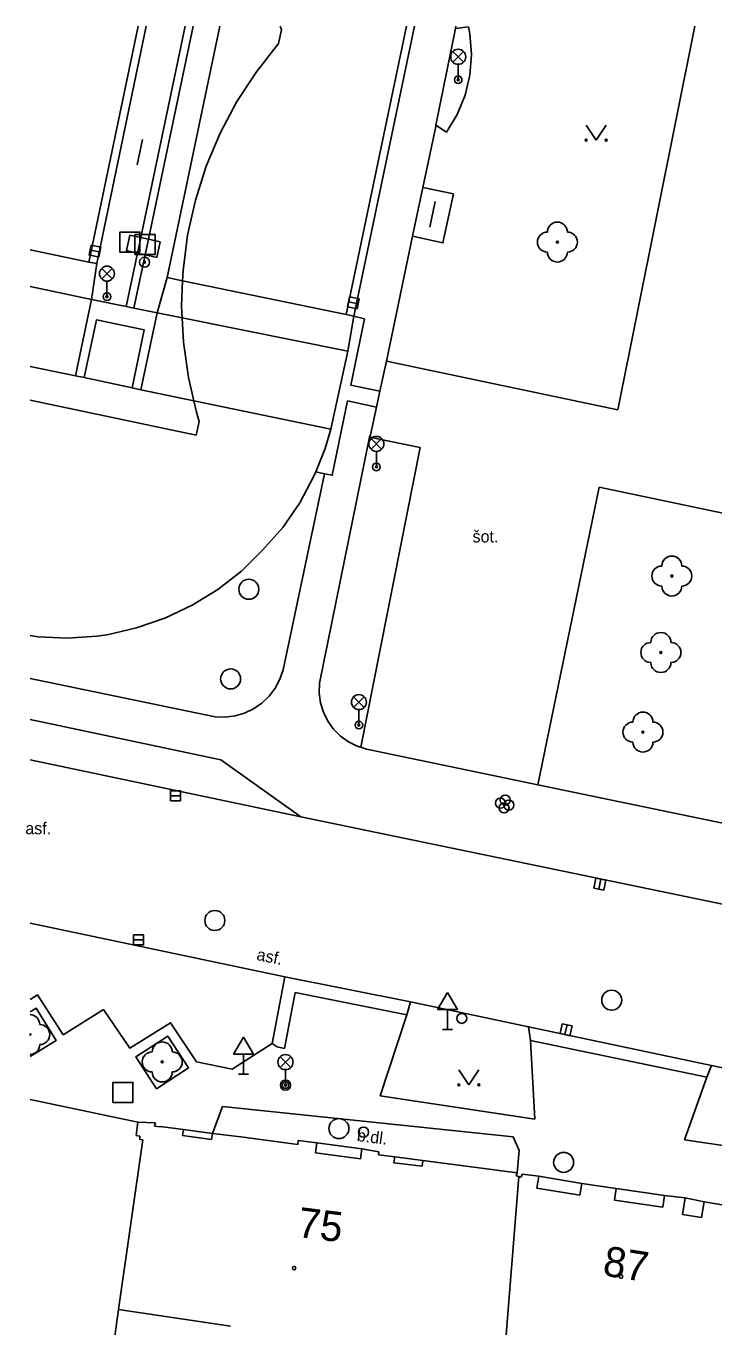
# Model space of a CAD drawing. Extents: x -642282 to -641982, y -1041678 to -1041427.
# Drawn here: x -642278.5 to -642244.2, y -1041493.9 to -1041428.9 of the extents above; entities that cross this region are included whole.
import ezdxf

# ---------------------------------------------------------------- set-up
doc = ezdxf.new("R2010")
doc.units = 0
for name, color, linetype in [('Budovy', 7, 'Continuous'), ('Neob_náplň-linie', 7, 'Continuous'), ('Popis povrchů', 7, 'Continuous'), ('Popis ČP_ ČE', 7, 'Continuous'), ('Rozhraní ploch 1', 7, 'Continuous'), ('Rozhraní ploch 2', 7, 'Continuous'), ('Sloupy_označník', 7, 'Continuous'), ('Zeleň - stromy', 7, 'Continuous'), ('Znaky doprava', 7, 'Continuous'), ('Znaky kanalizace', 7, 'Continuous'), ('Značky doprava', 7, 'Continuous'), ('Značky KM', 7, 'Continuous'), ('Značky předmětů', 7, 'Continuous'), ('Šachty ner_', 7, 'Continuous')]:
    doc.layers.add(name, color=color, linetype=linetype)

msp = doc.modelspace()

# ---------------------------------------------------------------- linework, layer by layer
at = {"layer": 'Budovy'}
for p, q in [((-642265.776, -1041429.092), (-642265.92, -1041429.777)), ((-642265.833, -1041428.899), (-642265.776, -1041429.092)), ((-642265.92, -1041429.777), (-642267.025, -1041431.182)), ((-642267.025, -1041431.182), (-642267.999, -1041432.68)), ((-642267.999, -1041432.68), (-642268.836, -1041434.259)), ((-642268.836, -1041434.259), (-642269.528, -1041435.907)), ((-642269.528, -1041435.907), (-642270.07, -1041437.61)), ((-642270.07, -1041437.61), (-642270.458, -1041439.355)), ((-642270.458, -1041439.355), (-642270.688, -1041441.127)), ((-642270.688, -1041441.127), (-642270.708, -1041441.64)), ((-642270.708, -1041441.64), (-642270.759, -1041442.913)), ((-642270.759, -1041442.913), (-642270.73, -1041443.493)), ((-642270.73, -1041443.493), (-642270.67, -1041444.698)), ((-642270.67, -1041444.698), (-642270.422, -1041446.467)), ((-642270.422, -1041446.467), (-642270.151, -1041447.631)), ((-642270.03, -1041449.35), (-642278.331, -1041447.61)), ((-642270.151, -1041447.631), (-642270.016, -1041448.208)), ((-642269.88, -1041448.67), (-642270.03, -1041449.35)), ((-642270.016, -1041448.208), (-642269.88, -1041448.67)), ((-642273.03, -1041484.37), (-642272.94, -1041483.7)), ((-642272.94, -1041483.7), (-642272.06, -1041483.74)), ((-642272.112, -1041483.9), (-642272.06, -1041483.74)), ((-642272.84, -1041484.4), (-642273.03, -1041484.37)), ((-642272.84, -1041484.56), (-642272.84, -1041484.4)), ((-642271.83, -1041483.941), (-642272.112, -1041483.9)), ((-642271.83, -1041483.92), (-642270.67, -1041484.07)), ((-642271.83, -1041483.92), (-642271.83, -1041483.941)), ((-642270.67, -1041484.07), (-642270.711, -1041484.367)), ((-642270.711, -1041484.367), (-642269.261, -1041484.567)), ((-642270.67, -1041484.07), (-642269.22, -1041484.27)), ((-642269.22, -1041484.27), (-642269.261, -1041484.567)), ((-642269.22, -1041484.27), (-642267.8, -1041484.44)), ((-642267.8, -1041484.44), (-642265.45, -1041484.75)), ((-642273.906, -1041493.066), (-642272.7, -1041484.58)), ((-642272.7, -1041484.58), (-642272.84, -1041484.56)), ((-642265.45, -1041484.75), (-642264.96, -1041484.81)), ((-642264.96, -1041484.81), (-642264.94, -1041484.62)), ((-642264.94, -1041484.62), (-642264, -1041484.74)), ((-642264, -1041484.74), (-642264.066, -1041485.236)), ((-642264, -1041484.74), (-642261.75, -1041485.04)), ((-642261.75, -1041485.04), (-642261.816, -1041485.536)), ((-642261.75, -1041485.04), (-642260.906, -1041485.181)), ((-642264.066, -1041485.236), (-642261.816, -1041485.536)), ((-642260.925, -1041485.326), (-642260.906, -1041485.181)), ((-642260.925, -1041485.326), (-642260.11, -1041485.43)), ((-642260.11, -1041485.43), (-642260.148, -1041485.728)), ((-642260.148, -1041485.728), (-642258.748, -1041485.908)), ((-642260.11, -1041485.43), (-642258.71, -1041485.61)), ((-642258.71, -1041485.61), (-642258.748, -1041485.908)), ((-642258.71, -1041485.61), (-642254, -1041486.24)), ((-642254, -1041486.24), (-642254.035, -1041486.386)), ((-642254.035, -1041486.386), (-642253.91, -1041486.416)), ((-642253.785, -1041486.446), (-642253.75, -1041486.3)), ((-642253.75, -1041486.3), (-642252.91, -1041486.4)), ((-642252.91, -1041486.4), (-642253.009, -1041486.992)), ((-642252.91, -1041486.4), (-642250.76, -1041486.76)), ((-642254.655, -1041495.751), (-642253.91, -1041486.416)), ((-642253.91, -1041486.416), (-642253.785, -1041486.446)), ((-642253.009, -1041486.992), (-642250.859, -1041487.352)), ((-642250.76, -1041486.76), (-642250.859, -1041487.352)), ((-642250.76, -1041486.76), (-642249.05, -1041487.01)), ((-642249.05, -1041487.01), (-642249.136, -1041487.604)), ((-642249.05, -1041487.01), (-642246.63, -1041487.36)), ((-642249.136, -1041487.604), (-642246.716, -1041487.954)), ((-642246.63, -1041487.36), (-642246.716, -1041487.954)), ((-642246.63, -1041487.36), (-642245.6, -1041487.48)), ((-642245.6, -1041487.48), (-642245.735, -1041488.315)), ((-642245.6, -1041487.48), (-642244.65, -1041487.68)), ((-642244.65, -1041487.68), (-642244.778, -1041488.47)), ((-642244.65, -1041487.68), (-642243.16, -1041487.93)), ((-642245.735, -1041488.315), (-642244.778, -1041488.47)), ((-642274.29, -1041495.77), (-642273.906, -1041493.066)), ((-642273.906, -1041493.066), (-642268.325, -1041493.892))]:
    msp.add_line(p, q, dxfattribs=at)
at = {"layer": 'Neob_náplň-linie'}
for p, q in [((-642272.98, -1041435.84), (-642272.71, -1041434.57)), ((-642258.36, -1041438.95), (-642258.09, -1041437.68))]:
    msp.add_line(p, q, dxfattribs=at)
at = {"layer": 'Rozhraní ploch 1'}
for p, q in [((-642275.39, -1041440.7), (-642272.934, -1041428.899)), ((-642271.48, -1041441.48), (-642268.852, -1041428.899)), ((-642259.121, -1041428.899), (-642262.15, -1041443.41)), ((-642257.08, -1041429.03), (-642257.052, -1041428.899)), ((-642257.08, -1041429.03), (-642256.42, -1041428.94)), ((-642258.05, -1041433.86), (-642257.52, -1041434.2)), ((-642260.515, -1041445.659), (-642259.22, -1041439.41)), ((-642275.39, -1041440.7), (-642278.331, -1041440.082)), ((-642275, -1041440.78), (-642275.39, -1041440.7)), ((-642275.27, -1041442.57), (-642275, -1041440.78)), ((-642271.99, -1041443.24), (-642271.48, -1041441.48)), ((-642270.708, -1041441.64), (-642271.48, -1041441.48)), ((-642278.331, -1041441.928), (-642275.27, -1041442.57)), ((-642262.54, -1041443.33), (-642270.708, -1041441.64)), ((-642275.27, -1041442.57), (-642276.07, -1041446.39)), ((-642271.99, -1041443.24), (-642272.79, -1041447.08)), ((-642271.99, -1041443.24), (-642270.73, -1041443.493)), ((-642270.73, -1041443.493), (-642262.46, -1041445.15)), ((-642276.07, -1041446.39), (-642278.331, -1041445.918)), ((-642260.86, -1041447.16), (-642260.515, -1041445.659)), ((-642263.3, -1041449.06), (-642270.151, -1041447.631)), ((-642261.371, -1041449.461), (-642261.32, -1041449.33)), ((-642263.87, -1041461.76), (-642261.371, -1041449.461)), ((-642265.69, -1041461.08), (-642263.62, -1041451.28)), ((-642269.09, -1041463.44), (-642278.331, -1041461.518)), ((-642278.331, -1041463.576), (-642268.8, -1041465.58)), ((-642264.81, -1041468.43), (-642278.331, -1041465.586)), ((-642268.8, -1041465.58), (-642264.81, -1041468.43)), ((-642252.953, -1041466.835), (-642261.36, -1041465.08)), ((-642231.773, -1041471.239), (-642252.953, -1041466.835)), ((-642232.19, -1041475.2), (-642264.81, -1041468.43)), ((-642265.6, -1041476.43), (-642278.331, -1041473.756)), ((-642266.23, -1041479.77), (-642265.6, -1041476.43)), ((-642265.6, -1041476.43), (-642259.32, -1041477.69)), ((-642259.51, -1041478.33), (-642265.09, -1041477.21)), ((-642259.32, -1041477.69), (-642259.51, -1041478.33)), ((-642253.43, -1041478.93), (-642259.32, -1041477.69)), ((-642276.68, -1041479.33), (-642274.66, -1041478.07)), ((-642260.84, -1041482.38), (-642259.51, -1041478.33)), ((-642244.29, -1041480.87), (-642253.43, -1041478.93)), ((-642253.43, -1041478.93), (-642253.32, -1041479.62)), ((-642268.24, -1041481.05), (-642266.23, -1041479.77)), ((-642253.32, -1041479.62), (-642253.11, -1041483.55)), ((-642253.32, -1041479.62), (-642244.52, -1041481.45)), ((-642244.29, -1041480.87), (-642244.52, -1041481.45)), ((-642244.29, -1041480.87), (-642218.1, -1041486.35)), ((-642244.52, -1041481.45), (-642245.63, -1041484.58)), ((-642253.11, -1041483.55), (-642260.84, -1041482.38)), ((-642278.331, -1041482.565), (-642272.94, -1041483.7)), ((-642245.63, -1041484.58), (-642220.43, -1041488.3))]:
    msp.add_line(p, q, dxfattribs=at)
for points in [[(-642258.06, -1041433.93), (-642258.05, -1041433.86), (-642257.08, -1041429.03)], [(-642257.52, -1041434.2), (-642256.987, -1041433.315), (-642256.596, -1041432.358), (-642256.357, -1041431.352), (-642256.277, -1041430.322), (-642256.356, -1041429.291), (-642256.42, -1041428.94)], [(-642259.22, -1041439.41), (-642258.7, -1041436.97), (-642258.06, -1041433.93)], [(-642258.7, -1041436.97), (-642257.18, -1041437.29), (-642257.7, -1041439.74), (-642259.22, -1041439.41)], [(-642275.27, -1041442.57), (-642273.53, -1041442.93), (-642273.14, -1041443.01), (-642271.99, -1041443.24)], [(-642263.3, -1041449.06), (-642262.46, -1041445.15), (-642262.15, -1041443.41), (-642262.54, -1041443.33)], [(-642262.15, -1041443.41), (-642261.62, -1041443.54), (-642262.3, -1041446.86), (-642260.86, -1041447.16)], [(-642270.151, -1041447.631), (-642272.79, -1041447.08), (-642273.23, -1041446.98), (-642275.63, -1041446.48), (-642276.07, -1041446.39)], [(-642261.32, -1041449.33), (-642261.03, -1041447.95), (-642260.86, -1041447.16)], [(-642264.05, -1041451.19), (-642263.62, -1041451.28), (-642263.23, -1041451.36), (-642262.47, -1041447.64), (-642261.03, -1041447.95)], [(-642266.72, -1041455.11), (-642265.705, -1041453.975), (-642264.861, -1041452.733), (-642264.153, -1041451.408), (-642264.05, -1041451.19), (-642263.591, -1041450.015), (-642263.3, -1041449.06)], [(-642274.48, -1041459.33), (-642273.017, -1041458.99), (-642271.598, -1041458.496), (-642270.24, -1041457.854), (-642268.957, -1041457.071), (-642267.765, -1041456.157), (-642266.72, -1041455.11)], [(-642278.331, -1041459.378), (-642277.921, -1041459.44), (-642276.458, -1041459.502), (-642274.996, -1041459.403), (-642274.48, -1041459.33)], [(-642269.09, -1041463.44), (-642268.589, -1041463.456), (-642268.092, -1041463.392), (-642267.612, -1041463.25), (-642267.16, -1041463.034), (-642266.748, -1041462.748), (-642266.387, -1041462.401), (-642266.085, -1041462.001), (-642265.851, -1041461.558), (-642265.69, -1041461.08)], [(-642263.87, -1041461.76), (-642263.884, -1041462.251), (-642263.819, -1041462.739), (-642263.676, -1041463.209), (-642263.458, -1041463.65), (-642263.172, -1041464.05), (-642262.825, -1041464.398), (-642262.426, -1041464.686), (-642261.986, -1041464.905), (-642261.809, -1041464.96), (-642261.516, -1041465.05), (-642261.36, -1041465.08)], [(-642265.09, -1041477.21), (-642265.62, -1041480.01), (-642265.98, -1041479.94), (-642266.23, -1041479.77)], [(-642278.331, -1041477.572), (-642277.96, -1041477.34), (-642276.68, -1041479.33)], [(-642274.66, -1041478.07), (-642273.35, -1041480), (-642271.31, -1041478.73), (-642270.02, -1041480.68), (-642268.24, -1041481.05)]]:
    msp.add_lwpolyline(points, dxfattribs=at)
at = {"layer": 'Rozhraní ploch 2'}
for p, q in [((-642275, -1041440.78), (-642272.527, -1041428.899)), ((-642270.587, -1041428.899), (-642272.805, -1041439.472)), ((-642270.18, -1041428.899), (-642272.416, -1041439.559)), ((-642259.527, -1041428.899), (-642262.54, -1041443.33)), ((-642248.968, -1041448.089), (-642245.122, -1041428.899)), ((-642260.515, -1041445.659), (-642248.968, -1041448.089)), ((-642258.834, -1041449.977), (-642261.809, -1041464.96)), ((-642261.371, -1041449.461), (-642258.834, -1041449.977)), ((-642252.953, -1041466.835), (-642249.894, -1041451.961)), ((-642249.894, -1041451.961), (-642228.798, -1041456.376)), ((-642269.22, -1041484.27), (-642268.71, -1041482.91)), ((-642268.71, -1041482.91), (-642254.2, -1041484.44)), ((-642254.2, -1041484.44), (-642253.9, -1041485.12)), ((-642253.9, -1041485.12), (-642254, -1041486.24))]:
    msp.add_line(p, q, dxfattribs=at)
for points in [[(-642272.805, -1041439.472), (-642272.969, -1041440.253), (-642273.53, -1041442.93)], [(-642273.35, -1041439.35), (-642273.52, -1041440.13), (-642272.969, -1041440.253), (-642272.58, -1041440.34), (-642272, -1041440.47), (-642271.83, -1041439.69), (-642272.416, -1041439.559), (-642272.805, -1041439.472), (-642273.35, -1041439.35)], [(-642272.416, -1041439.559), (-642272.58, -1041440.34), (-642273.14, -1041443.01)], [(-642273.23, -1041446.98), (-642272.63, -1041444.09), (-642275.02, -1041443.59), (-642275.63, -1041446.48)], [(-642278.331, -1041478.186), (-642278.03, -1041478), (-642277.03, -1041479.62), (-642278.331, -1041480.424)], [(-642272.01, -1041482.03), (-642273.05, -1041480.44), (-642271.45, -1041479.4), (-642270.41, -1041480.99), (-642272.01, -1041482.03)]]:
    msp.add_lwpolyline(points, dxfattribs=at)
at = {"layer": 'Sloupy_označník'}
for centre, radius in [((-642272.61, -1041440.71), 0.25), ((-642272.61, -1041440.71), 0.05), ((-642254.83, -1041467.75), 0.25), ((-642254.59, -1041467.6), 0.25), ((-642254.65, -1041467.99), 0.25), ((-642254.41, -1041467.85), 0.25), ((-642256.76, -1041478.51), 0.25), ((-642265.57, -1041481.85), 0.25), ((-642265.57, -1041481.85), 0.158), ((-642265.57, -1041481.85), 0.05), ((-642261.67, -1041484.2), 0.25)]:
    msp.add_circle(centre, radius, dxfattribs=at)
at = {"layer": 'Zeleň - stromy'}
msp.add_lwpolyline([(-642278.331, -1041479.274), (-642278.331, -1041479.366)], dxfattribs=at)
for centre in [(-642251.984, -1041439.702), (-642246.264, -1041456.396), (-642246.812, -1041460.219), (-642247.708, -1041464.2), (-642271.73, -1041480.69)]:
    msp.add_circle(centre, 0.05, dxfattribs=at)
for centre, radius, start, end in [((-642251.984, -1041439.202), 0.5, 0, 180), ((-642252.484, -1041439.702), 0.5, 90, 270), ((-642251.484, -1041439.702), 0.5, 270, 90), ((-642251.984, -1041440.202), 0.5, 180, 0), ((-642246.264, -1041455.896), 0.5, 0, 180), ((-642246.764, -1041456.396), 0.5, 90, 270), ((-642245.764, -1041456.396), 0.5, 270, 90), ((-642246.264, -1041456.896), 0.5, 180, 0), ((-642247.312, -1041460.219), 0.5, 90, 270), ((-642246.812, -1041459.719), 0.5, 0, 180), ((-642246.312, -1041460.219), 0.5, 270, 90), ((-642246.812, -1041460.719), 0.5, 180, 0), ((-642247.708, -1041463.7), 0.5, 0, 180), ((-642248.208, -1041464.2), 0.5, 90, 270), ((-642247.208, -1041464.2), 0.5, 270, 90), ((-642247.708, -1041464.7), 0.5, 180, 0), ((-642278.35, -1041478.82), 0.5, 0, 87.79437), ((-642277.85, -1041479.32), 0.5, 270, 90), ((-642278.35, -1041479.32), 0.05, 292.63502, 67.36498), ((-642278.35, -1041479.82), 0.5, 272.20563, 0), ((-642271.73, -1041480.19), 0.5, 0, 180), ((-642272.23, -1041480.69), 0.5, 90, 270), ((-642271.23, -1041480.69), 0.5, 270, 90), ((-642271.73, -1041481.19), 0.5, 180, 0)]:
    msp.add_arc(centre, radius, start, end, dxfattribs=at)
at = {"layer": 'Znaky doprava'}
for p, q in [((-642257.205, -1041430.175), (-642256.675, -1041430.705)), ((-642257.205, -1041430.705), (-642256.675, -1041430.175)), ((-642256.94, -1041431.59), (-642256.94, -1041430.815)), ((-642274.755, -1041441.015), (-642274.225, -1041441.545)), ((-642274.755, -1041441.545), (-642274.225, -1041441.015)), ((-642274.49, -1041442.43), (-642274.49, -1041441.655)), ((-642261.295, -1041449.525), (-642260.765, -1041450.055)), ((-642261.295, -1041450.055), (-642260.765, -1041449.525)), ((-642261.03, -1041450.94), (-642261.03, -1041450.165)), ((-642262.165, -1041462.435), (-642261.635, -1041462.965)), ((-642262.165, -1041462.965), (-642261.635, -1041462.435)), ((-642261.9, -1041463.85), (-642261.9, -1041463.075)), ((-642265.835, -1041480.434), (-642265.305, -1041480.965)), ((-642265.835, -1041480.965), (-642265.305, -1041480.434)), ((-642265.57, -1041481.85), (-642265.57, -1041481.075))]:
    msp.add_line(p, q, dxfattribs=at)
for centre, radius in [((-642256.94, -1041430.44), 0.375), ((-642256.94, -1041431.59), 0.19), ((-642256.94, -1041431.59), 0.05), ((-642274.49, -1041441.28), 0.375), ((-642274.49, -1041442.43), 0.19), ((-642274.49, -1041442.43), 0.05), ((-642261.03, -1041449.79), 0.375), ((-642261.03, -1041450.94), 0.19), ((-642261.03, -1041450.94), 0.05), ((-642261.9, -1041462.7), 0.375), ((-642261.9, -1041463.85), 0.19), ((-642261.9, -1041463.85), 0.05), ((-642265.57, -1041480.7), 0.375)]:
    msp.add_circle(centre, radius, dxfattribs=at)
at = {"layer": 'Znaky kanalizace'}
for p, q in [((-642274.846, -1041440.204), (-642275.334, -1041440.096)), ((-642262.425, -1041442.689), (-642261.935, -1041442.791)), ((-642271.31, -1041467.38), (-642270.81, -1041467.38)), ((-642249.809, -1041471.555), (-642249.911, -1041472.045)), ((-642273.16, -1041474.59), (-642272.66, -1041474.59)), ((-642251.495, -1041478.836), (-642251.605, -1041479.324))]:
    msp.add_line(p, q, dxfattribs=at)
for points in [[(-642274.792, -1041439.96), (-642275.28, -1041439.852), (-642275.388, -1041440.34), (-642274.9, -1041440.448)], [(-642262.476, -1041442.934), (-642261.986, -1041443.036), (-642261.884, -1041442.546), (-642262.374, -1041442.444)], [(-642271.31, -1041467.63), (-642270.81, -1041467.63), (-642270.81, -1041467.13), (-642271.31, -1041467.13)], [(-642250.054, -1041471.505), (-642250.155, -1041471.994), (-642249.666, -1041472.095), (-642249.565, -1041471.606)], [(-642273.16, -1041474.84), (-642272.66, -1041474.84), (-642272.66, -1041474.34), (-642273.16, -1041474.34)], [(-642251.739, -1041478.781), (-642251.849, -1041479.269), (-642251.361, -1041479.379), (-642251.251, -1041478.891)]]:
    msp.add_lwpolyline(points, close=True, dxfattribs=at)
for centre in [(-642267.4, -1041457.06), (-642268.31, -1041461.54), (-642269.1, -1041473.62), (-642249.27, -1041477.6), (-642262.9, -1041484.02), (-642251.67, -1041485.71)]:
    msp.add_circle(centre, 0.5, dxfattribs=at)
at = {"layer": 'Značky doprava'}
for p, q in [((-642257.98, -1041478.06), (-642257.48, -1041477.21)), ((-642257.48, -1041477.21), (-642256.98, -1041478.06)), ((-642257.98, -1041478.06), (-642256.98, -1041478.06)), ((-642257.48, -1041479.06), (-642257.48, -1041478.06)), ((-642257.73, -1041479.06), (-642257.23, -1041479.06)), ((-642268.16, -1041480.3), (-642267.66, -1041479.45)), ((-642267.66, -1041479.45), (-642267.16, -1041480.3)), ((-642268.16, -1041480.3), (-642267.16, -1041480.3)), ((-642267.66, -1041481.3), (-642267.66, -1041480.3)), ((-642267.91, -1041481.3), (-642267.41, -1041481.3))]:
    msp.add_line(p, q, dxfattribs=at)
at = {"layer": 'Značky KM'}
for p, q in [((-642250.547, -1041433.859), (-642250.047, -1041434.609)), ((-642250.047, -1041434.609), (-642249.547, -1041433.859)), ((-642256.91, -1041481.09), (-642256.41, -1041481.84)), ((-642256.41, -1041481.84), (-642255.91, -1041481.09))]:
    msp.add_line(p, q, dxfattribs=at)
for centre in [(-642250.547, -1041434.609), (-642249.547, -1041434.609), (-642256.91, -1041481.84), (-642255.91, -1041481.84)]:
    msp.add_circle(centre, 0.05, dxfattribs=at)
at = {"layer": 'Značky předmětů'}
for centre in [(-642265.14, -1041490.999), (-642248.801, -1041491.416)]:
    msp.add_circle(centre, 0.0875, dxfattribs=at)
at = {"layer": 'Šachty ner_'}
for points in [[(-642273.84, -1041440.2), (-642272.84, -1041440.2), (-642272.84, -1041439.2), (-642273.84, -1041439.2)], [(-642273.09, -1041440.33), (-642272.09, -1041440.33), (-642272.09, -1041439.33), (-642273.09, -1041439.33)], [(-642274.19, -1041482.71), (-642273.19, -1041482.71), (-642273.19, -1041481.71), (-642274.19, -1041481.71)]]:
    msp.add_lwpolyline(points, close=True, dxfattribs=at)

# ---------------------------------------------------------------- texts
at = {"layer": 'Popis povrchů'}
for s, p in [('šot.', (-642256.222, -1041454.718)), ('asf.', (-642278.57, -1041469.31))]:
    msp.add_text(s, height=0.6, dxfattribs=at).set_placement(p)
for s, rotation, p in [('asf.', 348.66044, (-642267.048, -1041475.589)), ('b.dl.', 352.72794, (-642262.027, -1041484.639))]:
    msp.add_text(s, height=0.6, rotation=rotation, dxfattribs=at).set_placement(p)
at = {"layer": 'Popis ČP_ ČE'}
for s, rotation, p in [('75', 352.986, (-642265.017, -1041489.433)), ('87', 351.118, (-642249.767, -1041491.355))]:
    msp.add_text(s, height=1.5, rotation=rotation, dxfattribs=at).set_placement(p)

doc.saveas('drawing.dxf')
